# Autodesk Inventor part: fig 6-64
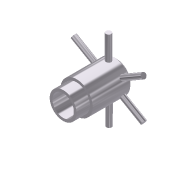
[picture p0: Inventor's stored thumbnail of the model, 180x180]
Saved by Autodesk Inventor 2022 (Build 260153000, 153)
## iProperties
Created: 2001-12
Part Number: fig 6-64
Document SubType Name: Modeling
Designer: Renu Muthoo
Density: 1 g/cm^3
Material: Generic
Appearance: Metal-AL-6061 (Polished)
Control State: 0
Master: False
Checked Out: False
Shininess: 77.0
Angle Display Precision: 2
Document Length Units: 11269
Document Angle Units: 11279
Document Time Units: 11290
Document Mass Units: 11283
Document Length Units Precision: 3
Document Angle Units Precision: 2
Compacted: True
Density: 0.0
Volumn: 0.0
Area: 0.0
PropertySet Name: Model Information
Author: Renu Muthoo
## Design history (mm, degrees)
sketch "Sketch2"
  geometry: L1 (-9.573, -4.327)-(-9.573, -5.327); L2 (-9.573, -5.327)-(-4.573, -5.327); L3 (-4.573, -5.327)-(-4.573, -6.327); L4 (-4.573, -6.327)-(9.427, -6.327); L5 (9.427, -6.327)-(10.427, -5.327); L6 (10.427, -5.327)-(10.427, -4.327); L7 (10.427, -4.327)-(-9.573, -4.327); L8 (-13.687, -0.327)-(14, -0.327)
  constraints: 16 end point, 5 parallel, 1 perpendicular, 1 vertical
  dimensions: "d9" = 20 distance of L6.end L1.start; "d10" = 5 distance of L1.end L2.end; "d11" = 12 diameter of L4 L8; "d12" = 10 diameter of L2 L8; "d13" = 8 diameter of L7 L8; "d14" = 45 deg angle of L5 L4; "d15" = 1 horizontal distance of L5.end L4.end
revolve "Revolution2" sketch "Sketch2" stored, may be unused: angle "d16" = 90 deg
workplane "Work Plane1"
workplane "Work Plane2"
sketch "Sketch3"
  geometry: L1 (-4, 8)-(4, 8) reference; C1 r 1 at (-0.098, 5)
  constraints: 1 centre point
  dimensions: "d18" = 3 distance from line of L1 C1.centre; "d19" = 2 diameter of C1
extrude "Extrusion1" join sketch "Sketch3" distance "d20" = 10; taper "d21" = 0 deg
pattern_circular "Circular Pattern3" dims angle "d29" = 360 deg
body "Solid1"
other parameters: "d17" = -1
